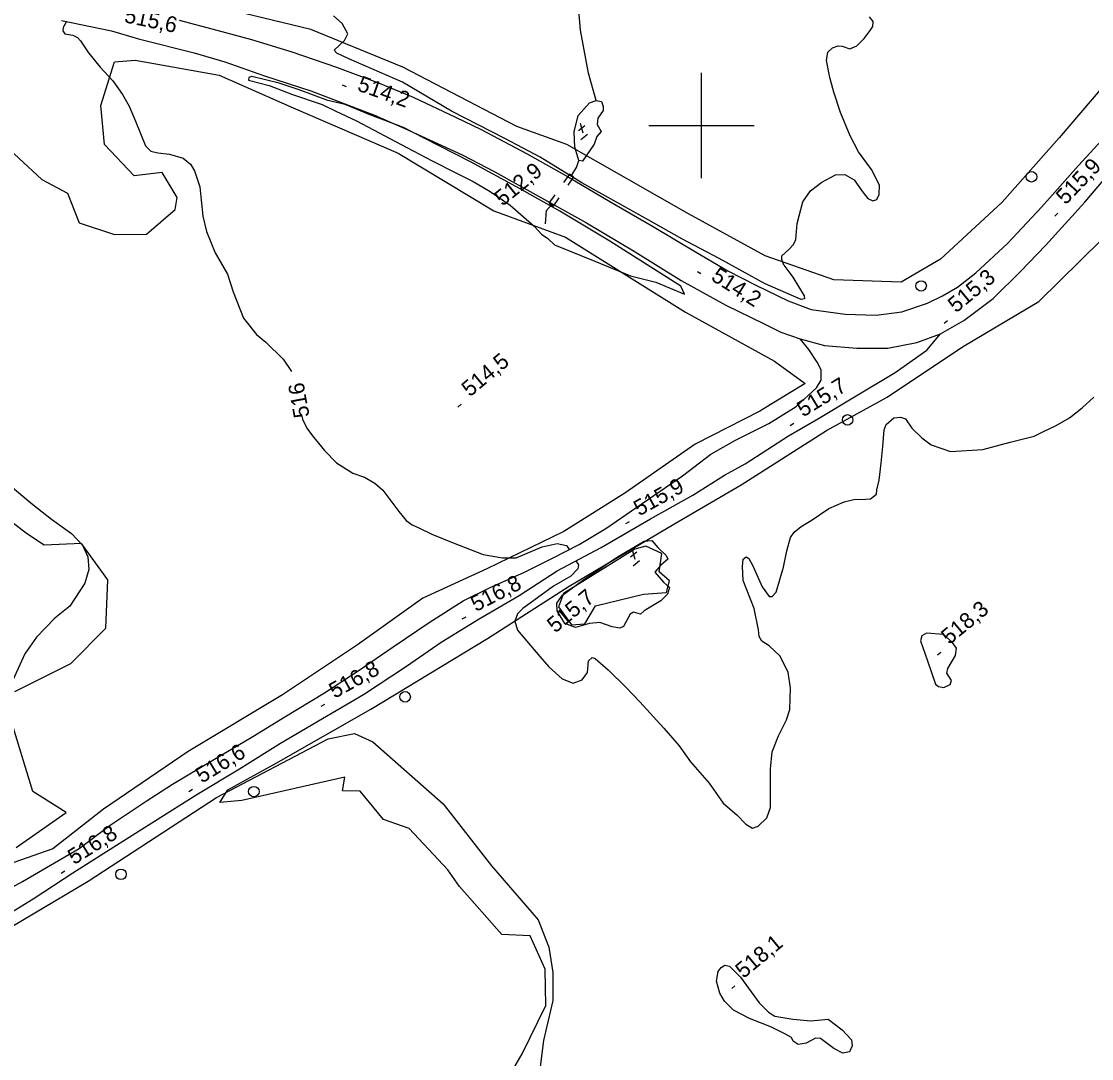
# Model space of a CAD drawing. Extents: x 347059 to 352153, y 6073752 to 6078601.
# Drawn here: x 349606.1 to 349911.2, y 6075334.1 to 6075629.7 of the extents above; entities that cross this region are included whole.
import ezdxf

# ---------------------------------------------------------------- set-up
doc = ezdxf.new("R2010")
doc.units = 0
for name, color, linetype in [('Level 19', 7, 'Continuous'), ('Level 2', 7, 'Continuous'), ('Level 21', 7, 'Continuous'), ('Level 26', 7, 'Continuous'), ('Level 3', 7, 'Continuous'), ('Level 36', 7, 'Continuous'), ('Level 4', 7, 'Continuous'), ('Level 44', 7, 'Continuous'), ('Level 61', 7, 'Continuous'), ('Level 7', 7, 'Continuous')]:
    doc.layers.add(name, color=color, linetype=linetype)

msp = doc.modelspace()

# ---------------------------------------------------------------- linework, layer by layer
at = {"layer": 'Level 19'}
for points in [[(349599.56, 6075380.85), (349606.39, 6075384.55), (349614.42, 6075389.19), (349622.63, 6075393.98), (349631.45, 6075400.59), (349641.69, 6075407.49), (349649.2, 6075412.3), (349661.13, 6075419.46), (349672.12, 6075425.92), (349681.23, 6075431.54), (349692.51, 6075438.31), (349702.36, 6075444.79), (349712.06, 6075451.45), (349722.32, 6075458.36), (349732.02, 6075464.56), (349739.78, 6075468.35), (349749.57, 6075472.72), (349757.47, 6075476.71), (349765.08, 6075480.6), (349772.67, 6075485.17), (349781.55, 6075491.29), (349794.56, 6075500.21), (349802.62, 6075506.33), (349809.67, 6075510.36), (349819.13, 6075515.06), (349826.92, 6075519.94), (349832.73, 6075525.31), (349834.08, 6075527.45), (349834.14, 6075530.42), (349832.97, 6075532.58), (349830.62, 6075536.19), (349828.13, 6075539.21)], [(349603.3, 6075375.88), (349609.48, 6075379.65), (349620.76, 6075387.03), (349631.4, 6075393.8), (349644.06, 6075401.81), (349656.13, 6075409.33), (349668.24, 6075416.73), (349679.97, 6075424.03), (349691.96, 6075431.02), (349703.65, 6075437.83), (349715.91, 6075445.96), (349725.75, 6075452.82), (349736.6, 6075459.46), (349748.03, 6075466.05), (349758.81, 6075473.16), (349771.41, 6075479.81), (349785.42, 6075487.97), (349797.5, 6075494.71), (349806.5, 6075500.4), (349812.41, 6075503.62), (349824.8, 6075511.56), (349833.34, 6075516.54), (349843.59, 6075522.67), (349855.2, 6075529.63), (349864.25, 6075536.04), (349868.11, 6075540.66)]]:
    msp.add_lwpolyline(points, dxfattribs=at)
at = {"layer": 'Level 2'}
for points in [[(349823.46, 6075560.24), (349825.97, 6075556.81), (349829.29, 6075551.48), (349829.37, 6075550.6), (349828.41, 6075550.46), (349828.41, 6075550.46), (349818.1, 6075554.9), (349804.97, 6075562.13), (349794.42, 6075567.69), (349784.81, 6075573.13), (349765.88, 6075583.72), (349754.01, 6075590.97), (349743.92, 6075596.33), (349728.7, 6075604.15), (349714.78, 6075612.4), (349699.47, 6075619.01), (349696.01, 6075620.64), (349695.26, 6075621.55), (349698.23, 6075624.23), (349699.19, 6075626.2), (349697.54, 6075629.14), (349695.11, 6075631.26)], [(349848.78, 6075578.55), (349849.92, 6075578.97), (349850.62, 6075580.37), (349850.76, 6075583.07), (349848.47, 6075587.51), (349844.76, 6075592.5), (349842.34, 6075597.1), (349839.56, 6075603.7), (349837.74, 6075609.49), (349836.54, 6075613.76), (349835.6, 6075618.52), (349836.01, 6075620.91), (349837.36, 6075622.18), (349838.95, 6075622.71), (349840.11, 6075622.61), (349842.26, 6075621.84), (349844.23, 6075622.7), (349846.38, 6075624.79), (349848.04, 6075627.14), (349848.86, 6075628.24), (349848.9, 6075629.63), (349847.83, 6075631.04)], [(349618.96, 6075629.67), (349618.03, 6075628.01), (349617.93, 6075627.01), (349618.49, 6075626.16), (349620.75, 6075625.79), (349622.12, 6075625.08), (349622.97, 6075624.2), (349625.22, 6075620.79), (349628.55, 6075616.7), (349632.18, 6075612.72), (349634.96, 6075608.83), (349636.87, 6075605.54), (349638.67, 6075601.24), (349641.51, 6075594.23), (349643.01, 6075592.71), (349644.97, 6075592.23), (349648.3, 6075591.82), (349652.21, 6075590.71), (349654.34, 6075589.05), (349655.44, 6075587.07), (349657.01, 6075582.57), (349657.36, 6075578.78), (349657.85, 6075574.18), (349658.89, 6075569.78), (349661.39, 6075563.78), (349664.83, 6075557.63), (349666.47, 6075552.64), (349669.46, 6075545.14), (349673.13, 6075540.44), (349675.82, 6075538.27), (349680.72, 6075533.4), (349683.1, 6075529.88)], [(349794.09, 6075554.29), (349773.88, 6075567.09), (349759.57, 6075575.66), (349748.09, 6075582.07), (349734.13, 6075589.64), (349720.89, 6075596.43), (349715.02, 6075599.49), (349705.25, 6075603.14), (349698.4, 6075606.06), (349693.42, 6075607.12), (349685.32, 6075610.17), (349679.56, 6075612.12), (349671.77, 6075613.98), (349670.95, 6075613.7), (349670.88, 6075612.98), (349676.76, 6075611.39), (349683.4, 6075608.84), (349691.81, 6075606.05), (349695.72, 6075604.15), (349701.65, 6075601.37), (349715.95, 6075593.75), (349723.24, 6075590), (349730.12, 6075586.42), (349734.89, 6075584.03), (349739.71, 6075581.26), (349745.4, 6075577.34), (349752.32, 6075571.37), (349754.34, 6075569.04), (349756.22, 6075567.8), (349758.1, 6075566.02), (349769.53, 6075561.34), (349779.71, 6075557.16), (349786.96, 6075555.35), (349795.1, 6075551.99), (349794.09, 6075554.29)], [(349823.46, 6075560.24), (349822.92, 6075561.83), (349822.86, 6075562.86), (349824.84, 6075564.67), (349826.2, 6075566.09), (349826.83, 6075567.58), (349827.27, 6075572.15), (349828.86, 6075578.24), (349831.03, 6075581.43), (349834.31, 6075583.93), (349838.14, 6075585.96), (349840.87, 6075586.09), (349843.54, 6075584.55), (349845.64, 6075581.45), (349847.37, 6075579.25), (349848.78, 6075578.55)], [(349824.34, 6075478.81), (349825.32, 6075482.66), (349826.35, 6075484.1), (349828.41, 6075485.77), (349831.26, 6075487.44), (349836.25, 6075490.84), (349840.64, 6075492.77), (349843.42, 6075493.43), (349846.7, 6075493.51), (349848.18, 6075493.68), (349849.82, 6075494.94), (349849.99, 6075496.17), (349850.58, 6075498.97), (349851.19, 6075503.81), (349851.64, 6075508.53), (349852.02, 6075513.32), (349852.65, 6075514.8), (349854.78, 6075516.74), (349856.7, 6075516.88), (349858.13, 6075516.46), (349859.89, 6075513.76), (349862.75, 6075511.04), (349865.45, 6075508.99), (349870.94, 6075507.15), (349880.21, 6075507.69), (349888, 6075509.82), (349894.79, 6075511.52), (349897.46, 6075512.84), (349901.11, 6075514.58), (349904.87, 6075516.68), (349908.47, 6075519.59), (349911.85, 6075522.6)], [(349685.98, 6075517.57), (349686.2, 6075516.35), (349687.48, 6075513.79), (349689.08, 6075511.63), (349692.49, 6075507.38), (349695.89, 6075503.93), (349700.62, 6075500.97), (349703.94, 6075499.78), (349706.88, 6075498.11), (349709.14, 6075496.12), (349713.66, 6075489.98), (349715.81, 6075487.49), (349717.54, 6075486.27), (349719.43, 6075485.34), (349723.15, 6075483.54)], [(349602.44, 6075497.85), (349609.39, 6075492.02), (349614.65, 6075487.85), (349620.42, 6075483.8), (349623.52, 6075480.42), (349625.05, 6075477.07), (349625.31, 6075473.45), (349624.24, 6075469.62), (349619.95, 6075463.07), (349615.69, 6075459.62), (349610.43, 6075454.25), (349607.13, 6075449.45), (349602.75, 6075439.91)], [(349723.15, 6075483.54), (349729.15, 6075481.13), (349737.75, 6075477.74), (349743.26, 6075476.82), (349747.17, 6075476.82), (349754.54, 6075479.98), (349758.87, 6075480.9), (349761.53, 6075480.29), (349762.24, 6075479.15)], [(349764.2, 6075476), (349764.93, 6075474.82), (349764.75, 6075473.64), (349762.74, 6075471.61), (349757.78, 6075468.78), (349749.05, 6075462.38), (349747.57, 6075460.82), (349746.78, 6075458.77), (349747.56, 6075456.17), (349753.93, 6075448.66), (349756.49, 6075445.72), (349760.24, 6075442.32), (349763.42, 6075441.14), (349766.01, 6075442.04), (349767.45, 6075444.11), (349767.81, 6075447.42), (349768.82, 6075448.44), (349769.66, 6075448.09), (349773.36, 6075444.91), (349778.52, 6075439.89), (349782.37, 6075435.76), (349789.25, 6075428.29), (349793.62, 6075423.25), (349796.86, 6075418.73), (349802.17, 6075412.61), (349806.2, 6075406.88), (349810.1, 6075403.62), (349812.59, 6075400.9), (349814.54, 6075399.74), (349816.17, 6075400.35), (349818.56, 6075402.71), (349819.62, 6075405.68), (349819.61, 6075416.56), (349820.15, 6075421.53), (349821.97, 6075426.11), (349824.22, 6075430.66), (349825.14, 6075433.64), (349825.31, 6075439.64), (349824.68, 6075444.26), (349822.31, 6075448.86), (349819.25, 6075451.77), (349817.17, 6075453.08), (349816.46, 6075454.37), (349816.23, 6075456.34), (349815.03, 6075462.38), (349811.88, 6075470.38), (349811.63, 6075474.38), (349811.84, 6075476.47), (349812.68, 6075477.06), (349813.44, 6075476.64), (349814.6, 6075474.53), (349817.32, 6075468.59), (349819.31, 6075465.84), (349820.17, 6075465.77), (349821.26, 6075467), (349823.39, 6075474.17), (349824.34, 6075478.81)], [(349870.2, 6075445.27), (349872.39, 6075449.03), (349872.66, 6075451.09), (349871.46, 6075452.74), (349868.95, 6075454.97), (349864.09, 6075455.37), (349862.83, 6075454.62), (349862.37, 6075453.16), (349864.43, 6075447.43), (349866.7, 6075440.8), (349867.55, 6075440.14), (349869.08, 6075439.84), (349870.85, 6075440.71), (349871.24, 6075441.89), (349869.95, 6075443.92), (349870.2, 6075445.27)], [(349836.11, 6075345.34), (349840.09, 6075342.3), (349842.71, 6075339.44), (349842.96, 6075337.75), (349842.13, 6075336.08), (349840.3, 6075335.7), (349837.72, 6075336.97), (349833.87, 6075339.86), (349832.51, 6075339.89), (349829.82, 6075338.49), (349827.56, 6075338.14), (349826.11, 6075339.04), (349825.68, 6075340.16), (349823.73, 6075341.17), (349819.96, 6075343.04), (349813.63, 6075345.52), (349809.11, 6075347.95), (349806.53, 6075350.45), (349805.17, 6075352.8), (349804.24, 6075356.19), (349804.71, 6075358.91), (349805.58, 6075360.08), (349806.63, 6075360.73), (349807.98, 6075360.41), (349811.09, 6075357.29), (349816.45, 6075350.02), (349819.08, 6075347.3), (349820.88, 6075346.16), (349826.02, 6075345.35), (349831.11, 6075344.91), (349836.11, 6075345.34)]]:
    msp.add_lwpolyline(points, dxfattribs=at)
at = {"layer": 'Level 21'}
for points in [[(349617.57, 6075629.96), (349631.8, 6075626.97), (349639.53, 6075624.74), (349655.32, 6075620.7), (349664.1, 6075618.2), (349675.46, 6075614.16), (349688.66, 6075609.9), (349706.76, 6075602.94), (349715.44, 6075599.22), (349731.72, 6075591.64), (349741.09, 6075586.83), (349755.21, 6075578.95)], [(349651.1, 6075630.03), (349661.81, 6075627.25), (349671.7, 6075624.56), (349683.21, 6075621), (349695.98, 6075616.64), (349708.35, 6075612.03)], [(349708.35, 6075612.03), (349717.8, 6075608.12), (349729.86, 6075602.41), (349737.21, 6075598.9), (349750.08, 6075592.1), (349761.76, 6075585.54), (349773.84, 6075578.4), (349786.04, 6075571.3), (349798.26, 6075564.07), (349807.49, 6075558.63), (349815.44, 6075554.57), (349824.66, 6075550.06), (349831.26, 6075547.56), (349840.97, 6075546.24), (349849.8, 6075546.01), (349857.11, 6075546.97), (349864.44, 6075549.39), (349868.64, 6075551.47), (349872.95, 6075553.97), (349878.2, 6075558.01), (349887.19, 6075566.44), (349896.89, 6075576.78), (349907.47, 6075588.64), (349918.49, 6075600.62)], [(349755.21, 6075578.95), (349767.22, 6075572.26), (349781.05, 6075563.99), (349794.15, 6075555.88), (349806.88, 6075548.86), (349817.88, 6075543.48), (349822.56, 6075541.11), (349828.13, 6075539.21), (349835.02, 6075537.36), (349844.29, 6075536.58), (349853.05, 6075536.61), (349861.41, 6075538.22), (349868.11, 6075540.66), (349874.74, 6075544.49), (349883.11, 6075550.71), (349891.05, 6075558.49), (349898.08, 6075565.8), (349909.25, 6075578.14), (349919.48, 6075590.24)]]:
    msp.add_lwpolyline(points, dxfattribs=at)
at = {"layer": 'Level 26'}
for p, q in [((349762.33, 6075586.2), (349760.69, 6075583.83)), ((349763.54, 6075585.36), (349761.87, 6075583.01)), ((349763.54, 6075585.36), (349762.33, 6075586.2)), ((349756.59, 6075577.92), (349758.25, 6075580.27)), ((349757.81, 6075577.08), (349759.44, 6075579.45)), ((349756.59, 6075577.92), (349757.81, 6075577.08))]:
    msp.add_line(p, q, dxfattribs=at)
at = {"layer": 'Level 3'}
for p, q in [((349697.55, 6075611.58), (349698.69, 6075611.18)), ((349764.92, 6075598.58), (349766.74, 6075600.06)), ((349765.4, 6075600.7), (349766.2, 6075597.96)), ((349765.62, 6075596.05), (349767.49, 6075597.57)), ((349900.73, 6075574.16), (349901.57, 6075575.02)), ((349798.81, 6075558.47), (349799.82, 6075557.83)), ((349869.18, 6075543.74), (349870.1, 6075544.5)), ((349730.57, 6075519.8), (349731.49, 6075520.57)), ((349825.24, 6075514.58), (349826.26, 6075515.21)), ((349778.44, 6075486.57), (349779.49, 6075487.15)), ((349779.74, 6075477.07), (349781.54, 6075478.56)), ((349780.2, 6075479.2), (349781.02, 6075476.46)), ((349780.46, 6075474.55), (349782.31, 6075476.08)), ((349731.79, 6075459.43), (349732.86, 6075459.97)), ((349867.27, 6075449.18), (349868.19, 6075449.95)), ((349691.59, 6075434.58), (349692.64, 6075435.16)), ((349653.84, 6075410.24), (349654.87, 6075410.87)), ((349617.44, 6075386.96), (349618.46, 6075387.6)), ((349808.6, 6075354.07), (349809.52, 6075354.84))]:
    msp.add_line(p, q, dxfattribs=at)
at = {"layer": 'Level 36'}
for centre in [(349894.05, 6075585.41), (349862.58, 6075554.31), (349841.63, 6075516.13), (349715.5, 6075437.21), (349672.37, 6075410.2), (349634.5, 6075386.63)]:
    msp.add_circle(centre, 1.5, dxfattribs=at)
at = {"layer": 'Level 4'}
for points in [[(349769.98, 6075607.13), (349767.73, 6075614.97), (349765.51, 6075627.24), (349764.19, 6075642.77)], [(349769.98, 6075607.13), (349771.49, 6075606.86), (349771.95, 6075605.47), (349771.97, 6075604.33), (349770.4, 6075602.08), (349770.2, 6075600.28), (349771.35, 6075598.32), (349770.18, 6075596.87), (349769.41, 6075594.67), (349766.07, 6075589.84), (349765.01, 6075590.02), (349763.86, 6075593.84), (349763.67, 6075598.24), (349764.87, 6075602.89), (349768.06, 6075606.51), (349769.98, 6075607.13)], [(349762.94, 6075585.81), (349764.38, 6075588.03), (349765.01, 6075590.02)], [(349755.53, 6075571.97), (349755.83, 6075575.85), (349757.19, 6075577.47)], [(349786.72, 6075472.73), (349789.14, 6075469.87), (349790.87, 6075468.41), (349790.31, 6075466.42), (349788.37, 6075464.55), (349783.62, 6075461.69), (349782.55, 6075460.78), (349780.62, 6075461.29), (349779.66, 6075460.8), (349777.74, 6075457.26), (349776.66, 6075456.73), (349774.47, 6075457.18), (349770.99, 6075458.38), (349768.08, 6075458.06), (349764.06, 6075456.97), (349761.03, 6075458.08), (349758.84, 6075461.75), (349758.7, 6075463.94), (349760.39, 6075466.21), (349766.04, 6075470.37), (349775.79, 6075476.91), (349783.67, 6075481.58), (349785.84, 6075481.79), (349787.51, 6075479.76), (349789.95, 6075477.53), (349790.43, 6075476.4), (349788.33, 6075474.62), (349786.72, 6075472.73)]]:
    msp.add_lwpolyline(points, dxfattribs=at)
at = {"layer": 'Level 44'}
for points in [[(349917.45, 6075614.67), (349901.91, 6075596.48), (349885.71, 6075578.19), (349868.13, 6075561.97), (349856.88, 6075555.38), (349837.71, 6075556.08), (349818.09, 6075562.85), (349796.27, 6075574.87), (349761.55, 6075594.66), (349747.33, 6075599.78), (349714.83, 6075616.62), (349688.65, 6075627.41), (349656.3, 6075635.16)], [(349592.21, 6075602.92), (349611.97, 6075584.64), (349619.25, 6075580.77), (349622.58, 6075572.28), (349632.7, 6075568.97), (349641.74, 6075569.11), (349649.93, 6075576.05), (349650.49, 6075579.52), (349646.21, 6075586.62), (349638.25, 6075585.72), (349629.78, 6075594.61), (349628.74, 6075605.75), (349632.66, 6075618.16), (349638.54, 6075618.68), (349662.47, 6075614.34), (349683.58, 6075605.09), (349713.5, 6075592.15), (349740.81, 6075575.68), (349761.21, 6075568.21), (349795.42, 6075546.82), (349820.77, 6075532.9), (349829.51, 6075526.48), (349816.57, 6075518.58), (349798.21, 6075509.21), (349778.14, 6075495.23), (349760.74, 6075484.34), (349738.77, 6075473.73), (349720.5, 6075465.3), (349701.92, 6075451.98), (349680.56, 6075437.81), (349653.61, 6075421.63), (349629.49, 6075405.18), (349615.07, 6075393.85), (349603.93, 6075389.97)], [(349743.77, 6075326.63), (349748.83, 6075335.46), (349755.65, 6075349.28), (349755.42, 6075359.6), (349751.18, 6075369.13), (349743.07, 6075369.45), (349730.96, 6075383.19), (349727.68, 6075387.9), (349716.62, 6075399.65), (349709.35, 6075402.23), (349702.66, 6075410.33), (349697.64, 6075410.38), (349698.31, 6075414.31), (349668.95, 6075407.62), (349662.71, 6075407.1), (349664.96, 6075410.7), (349678.7, 6075418.29), (349705.74, 6075433.67), (349738.95, 6075453.86), (349762.28, 6075468.79), (349792.07, 6075486.44), (349811.25, 6075497.65), (349835.59, 6075513.12), (349852.86, 6075522.6), (349874.37, 6075536.93), (349896.11, 6075549.91), (349913.98, 6075567.45)], [(349604.24, 6075438.72), (349620.21, 6075446.69), (349630.16, 6075456.79), (349630.77, 6075470.52), (349623.24, 6075480.91), (349612.62, 6075480.39), (349607.54, 6075483.78), (349594.89, 6075493.4)], [(349759.18, 6075462.81), (349762.93, 6075457.7), (349766.75, 6075458.02), (349769.77, 6075463.17), (349783.42, 6075466.42), (349789.97, 6075466.9), (349790.85, 6075470.25), (349787.95, 6075472.85), (349788.67, 6075478.05), (349784.07, 6075480.15), (349781.02, 6075479.26), (349760.68, 6075466.68), (349759.18, 6075462.81)], [(349604.63, 6075394.24), (349618.86, 6075404.27), (349609.39, 6075410.22), (349602.81, 6075431.67)]]:
    msp.add_lwpolyline(points, dxfattribs=at)
at = {"layer": 'Level 61'}
for p, q in [((349800, 6075585), (349800, 6075615)), ((349785, 6075600), (349815, 6075600))]:
    msp.add_line(p, q, dxfattribs=at)
at = {"layer": 'Level 7'}
for points in [[(349791.27, 6075063.8), (349789.37, 6075094.97), (349781.47, 6075110.61), (349756.2, 6075133.07), (349737.24, 6075153.35), (349720.6, 6075168.66), (349717.82, 6075172.37), (349694.61, 6075206.44), (349670.09, 6075226.15), (349635.36, 6075249.78), (349613.59, 6075260.35), (349607.48, 6075267.69), (349606.14, 6075292.17), (349591.24, 6075306.46), (349578.73, 6075314.23), (349572.6, 6075321.59), (349570.7, 6075328.24), (349577.66, 6075353.71), (349593.72, 6075366.06), (349625.18, 6075384.67), (349661.73, 6075408.49), (349693.55, 6075425.26), (349701.1, 6075426.73), (349706.34, 6075424.42)], [(349593.72, 6075366.06), (349625.18, 6075384.67), (349661.73, 6075408.49), (349693.55, 6075425.26), (349701.1, 6075426.73), (349706.34, 6075424.42), (349726.37, 6075406.75), (349740.11, 6075389.01), (349753.38, 6075373.65), (349756.47, 6075365.89), (349757.64, 6075358.64), (349757.58, 6075350.67), (349754.92, 6075339.28), (349752.65, 6075321.23), (349752.57, 6075302), (349757.55, 6075282.49), (349768.1, 6075262.84), (349781.77, 6075237.96), (349788.12, 6075230.28), (349792.36, 6075217.33)], [(349706.34, 6075424.42), (349706.34, 6075424.42), (349726.37, 6075406.75), (349740.11, 6075389.01), (349753.38, 6075373.65), (349756.47, 6075365.89), (349757.64, 6075358.64), (349757.58, 6075350.67), (349754.92, 6075339.28), (349752.65, 6075321.23), (349752.57, 6075302), (349757.55, 6075282.49), (349768.1, 6075262.84), (349781.77, 6075237.96), (349788.12, 6075230.28), (349792.36, 6075217.33)]]:
    msp.add_lwpolyline(points, dxfattribs=at)

# ---------------------------------------------------------------- texts
at = {"layer": 'Level 2'}
msp.add_text('516', height=4.5, rotation=100.3472, dxfattribs=at).set_placement((349688.3, 6075517.17))
at = {"layer": 'Level 3'}
for s, rotation, p in [('515,6', 348.0645, (349635.24, 6075629.5)), ('514,2', 340.4432, (349701.6, 6075610.09)), ('  512,9', 39.1201, (349740.69, 6075574.76)), ('515,9', 46.0725, (349903.77, 6075577.23)), ('514,2', 327.7823, (349802.44, 6075556.12)), ('515,3', 39.62, (349872.54, 6075546.45)), ('514,5', 39.62, (349733.93, 6075522.52)), ('515,7', 31.4899, (349828.95, 6075516.8)), ('515,9', 28.9298, (349782.24, 6075488.61)), ('516,8', 26.9778, (349735.66, 6075461.34)), ('  515,7', 39.57, (349755.71, 6075453.08)), ('518,3', 39.62, (349870.63, 6075451.9)), ('516,8', 28.8357, (349695.4, 6075436.62)), ('516,6', 31.3528, (349657.56, 6075412.45)), ('516,8', 31.975, (349621.13, 6075389.21)), ('518,1', 39.62, (349811.96, 6075356.78))]:
    msp.add_text(s, height=4.5, rotation=rotation, dxfattribs=at).set_placement(p)

doc.saveas('drawing.dxf')
